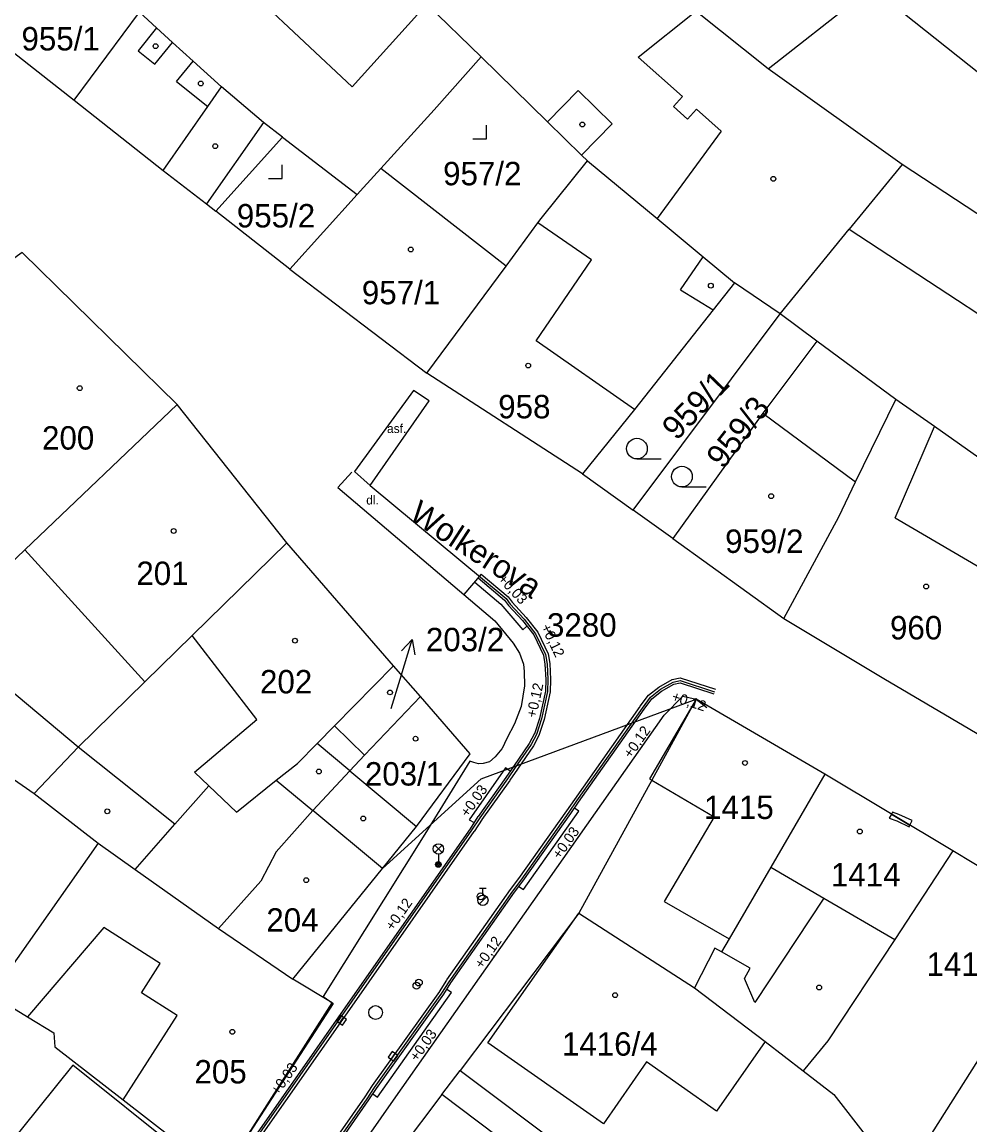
# Model space of a CAD drawing. Extents: x -600849 to -599899, y -1204328 to -1203436.
# Drawn here: x -600363.4 to -600294.6, y -1203715.5 to -1203635.4 of the extents above; entities that cross this region are included whole.
import ezdxf

# ---------------------------------------------------------------- set-up
doc = ezdxf.new("R2010")
doc.units = 0
for name, color, linetype in [('Vrstva 1', 7, 'Continuous'), ('Vrstva 10', 7, 'Continuous'), ('Vrstva 11', 7, 'Continuous'), ('Vrstva 13', 7, 'Continuous'), ('Vrstva 2', 7, 'Continuous'), ('Vrstva 27', 7, 'Continuous'), ('Vrstva 28', 7, 'Continuous'), ('Vrstva 3', 7, 'Continuous'), ('Vrstva 33', 7, 'Continuous'), ('Vrstva 4', 7, 'Continuous'), ('Vrstva 40', 7, 'Continuous'), ('Vrstva 42', 7, 'Continuous'), ('Vrstva 5', 7, 'Continuous'), ('Vrstva 7', 7, 'Continuous')]:
    doc.layers.add(name, color=color, linetype=linetype)

msp = doc.modelspace()

# ---------------------------------------------------------------- linework, layer by layer
at = {"layer": 'Vrstva 1'}
for p, q in [((-600309.22, -1203638.82), (-600301.72, -1203632.94)), ((-600366.05, -1203636.05), (-600359.62, -1203641.11)), ((-600333.47, -1203641.81), (-600330.07, -1203637.95)), ((-600359.62, -1203641.11), (-600353.15, -1203646.2)), ((-600337.36, -1203646.05), (-600333.47, -1203641.81)), ((-600349.33, -1203649.16), (-600344.49, -1203643.78)), ((-600344.49, -1203643.78), (-600339.08, -1203647.96)), ((-600328.26, -1203653.15), (-600337.36, -1203646.05)), ((-600339.08, -1203647.96), (-600343.95, -1203653.36)), ((-600343.95, -1203653.36), (-600349.33, -1203649.16)), ((-600328.26, -1203653.15), (-600325.94, -1203650.01)), ((-600343.95, -1203653.36), (-600334.01, -1203660.91)), ((-600334.01, -1203660.91), (-600328.26, -1203653.15)), ((-600308.36, -1203656.62), (-600311.66, -1203654.37)), ((-600319.02, -1203670.87), (-600308.36, -1203656.62)), ((-600305.68, -1203658.6), (-600308.36, -1203656.62)), ((-600299.96, -1203662.82), (-600305.68, -1203658.6)), ((-600322.7, -1203668.24), (-600334.01, -1203660.91)), ((-600344.18, -1203673.23), (-600352.14, -1203663.19)), ((-600302.87, -1203668.82), (-600299.96, -1203662.82)), ((-600318.92, -1203663.55), (-600322.7, -1203668.24)), ((-600322.7, -1203668.24), (-600319.02, -1203670.87)), ((-600316.15, -1203672.93), (-600319.02, -1203670.87)), ((-600316.15, -1203672.93), (-600308.08, -1203678.72)), ((-600336.42, -1203682.16), (-600344.18, -1203673.23)), ((-600340.71, -1203686.52), (-600336.42, -1203682.16)), ((-600334.48, -1203684.39), (-600336.42, -1203682.16)), ((-600305.11, -1203690.04), (-600314.45, -1203684.58)), ((-600295.8, -1203695.61), (-600305.11, -1203690.04)), ((-600362.52, -1203691.44), (-600357.88, -1203695.04)), ((-600337.24, -1203696.89), (-600334.76, -1203693.83)), ((-600357.88, -1203695.04), (-600365.63, -1203706.06)), ((-600357.88, -1203695.04), (-600355.19, -1203696.95)), ((-600287.54, -1203700.59), (-600295.8, -1203695.61)), ((-600343.75, -1203704.92), (-600337.24, -1203696.89)), ((-600322.98, -1203700.12), (-600331.6, -1203711.54)), ((-600322.98, -1203700.12), (-600314.57, -1203705.54)), ((-600287.54, -1203700.59), (-600299.56, -1203719.57)), ((-600340.89, -1203706.64), (-600343.75, -1203704.92)), ((-600314.57, -1203705.54), (-600309.44, -1203709.45)), ((-600348.91, -1203719.22), (-600340.89, -1203706.64)), ((-600309.44, -1203709.45), (-600306.67, -1203711.58)), ((-600332.92, -1203713.3), (-600331.6, -1203711.54)), ((-600331.6, -1203711.54), (-600311.99, -1203726.24)), ((-600332.92, -1203713.3), (-600339.11, -1203721.5)), ((-600314.72, -1203726.98), (-600332.92, -1203713.3))]:
    msp.add_line(p, q, dxfattribs=at)
for points in [[(-600330.07, -1203637.95), (-600334.01, -1203634.13), (-600341.44, -1203626.9), (-600343.88, -1203624.53), (-600348.59, -1203618.67)], [(-600309.22, -1203638.82), (-600314.48, -1203634.64), (-600317.23, -1203632.11)], [(-600344.49, -1203643.78), (-600345.86, -1203642.72), (-600348.93, -1203640.13), (-600350.99, -1203638.26), (-600352.47, -1203636.91), (-600353.63, -1203635.85), (-600354.88, -1203634.71)], [(-600299.45, -1203634.74), (-600278.65, -1203651.25), (-600263.23, -1203661.57), (-600241.56, -1203672.31)], [(-600322.35, -1203645.5), (-600322.77, -1203645.09), (-600325.25, -1203642.67), (-600330.07, -1203637.95)], [(-600282.53, -1203656.9), (-600299.5, -1203645.77), (-600309.22, -1203638.82)], [(-600325.94, -1203650.01), (-600325.71, -1203649.7), (-600322.35, -1203645.5)], [(-600322.35, -1203645.5), (-600317.29, -1203649.7), (-600313.95, -1203652.47), (-600311.66, -1203654.37)], [(-600353.15, -1203646.2), (-600350.01, -1203648.63), (-600349.33, -1203649.16)], [(-600339.08, -1203647.96), (-600338.62, -1203647.44), (-600337.36, -1203646.05)], [(-600308.36, -1203656.62), (-600303.33, -1203650.46), (-600286.14, -1203661.75), (-600282.53, -1203656.9)], [(-600352.14, -1203663.19), (-600363.4, -1203652.15), (-600364.16, -1203652.72)], [(-600311.66, -1203654.37), (-600313.21, -1203656.33), (-600318.92, -1203663.55)], [(-600305.68, -1203658.6), (-600309.62, -1203663.83), (-600316.15, -1203672.93)], [(-600373.17, -1203683.31), (-600369.43, -1203679.61), (-600368.04, -1203678.14), (-600367.92, -1203678.25), (-600363.2, -1203673.74), (-600352.14, -1203663.19)], [(-600284.69, -1203673.58), (-600288.48, -1203670.91), (-600297.15, -1203664.8), (-600299.96, -1203662.82)], [(-600308.08, -1203678.72), (-600304.09, -1203671.35), (-600302.87, -1203668.82)], [(-600362.52, -1203691.44), (-600359.32, -1203688.08), (-600354.48, -1203683.34), (-600351.05, -1203679.97), (-600344.18, -1203673.23)], [(-600308.08, -1203678.72), (-600300.83, -1203683.09), (-600292.82, -1203687.81)], [(-600373.17, -1203683.31), (-600366.91, -1203688.4), (-600362.52, -1203691.44)], [(-600334.48, -1203684.39), (-600338.53, -1203688.66), (-600340.71, -1203686.52)], [(-600337.24, -1203696.89), (-600330.06, -1203690.37), (-600314.45, -1203684.58)], [(-600334.76, -1203693.83), (-600330.86, -1203688.56), (-600334.48, -1203684.39)], [(-600314.45, -1203684.58), (-600317.68, -1203690.47), (-600322.98, -1203700.12)], [(-600344.94, -1203690.48), (-600343.4, -1203689.26), (-600341.97, -1203687.81), (-600340.71, -1203686.52)], [(-600355.19, -1203696.95), (-600352.3, -1203693.66), (-600349.85, -1203690.87), (-600347.84, -1203692.79), (-600344.94, -1203690.48)], [(-600344.94, -1203690.48), (-600342.3, -1203692.68), (-600339.6, -1203689.79), (-600334.76, -1203693.83)], [(-600305.11, -1203690.04), (-600309.03, -1203696.78), (-600312.05, -1203701.98), (-600312.6, -1203702.94), (-600313.09, -1203702.67), (-600314.57, -1203705.54)], [(-600295.8, -1203695.61), (-600300.03, -1203702.03), (-600304.88, -1203709.39), (-600306.67, -1203711.58)], [(-600355.19, -1203696.95), (-600349.13, -1203701.25), (-600343.75, -1203704.92)], [(-600309.44, -1203709.45), (-600312.98, -1203714.49), (-600318.05, -1203710.93), (-600321.19, -1203715.42), (-600329.58, -1203709.54), (-600322.98, -1203700.12)], [(-600365.63, -1203706.06), (-600363, -1203707.66), (-600361.09, -1203708.81), (-600361.02, -1203709.84), (-600356.07, -1203713.68), (-600348.91, -1203719.22)], [(-600306.67, -1203711.58), (-600304.45, -1203713.29), (-600299.56, -1203719.57)]]:
    msp.add_lwpolyline(points, dxfattribs=at)
at = {"layer": 'Vrstva 10'}
for p, q in [((-600339.26, -1203668.07), (-600338.12, -1203669.07)), ((-600338.12, -1203669.07), (-600328.25, -1203677.29)), ((-600328.25, -1203677.29), (-600327.97, -1203677.68)), ((-600327.97, -1203677.68), (-600326.95, -1203678.78)), ((-600326.95, -1203678.78), (-600326.12, -1203679.84)), ((-600326.12, -1203679.84), (-600325.39, -1203681.35)), ((-600325.39, -1203681.35), (-600325.28, -1203682.04)), ((-600325.28, -1203682.04), (-600325.22, -1203683.16)), ((-600325.22, -1203683.16), (-600325.25, -1203684.03)), ((-600316.12, -1203683.36), (-600315.61, -1203683.24)), ((-600315.61, -1203683.24), (-600313.12, -1203684.05)), ((-600325.25, -1203684.03), (-600325.68, -1203686.02)), ((-600317.77, -1203684.45), (-600317.04, -1203683.87)), ((-600317.04, -1203683.87), (-600316.12, -1203683.36)), ((-600318.35, -1203685.23), (-600317.77, -1203684.45)), ((-600323.11, -1203691.98), (-600318.35, -1203685.23)), ((-600325.68, -1203686.02), (-600326.05, -1203687.15)), ((-600326.05, -1203687.15), (-600326.44, -1203687.87)), ((-600326.44, -1203687.87), (-600327.6, -1203689.55)), ((-600327.6, -1203689.55), (-600328.14, -1203690.36)), ((-600328.14, -1203690.36), (-600330.17, -1203693.2)), ((-600323.68, -1203692.8), (-600323.11, -1203691.98)), ((-600327.17, -1203697.72), (-600323.68, -1203692.8)), ((-600330.17, -1203693.2), (-600330.76, -1203694.1)), ((-600330.76, -1203694.1), (-600339.46, -1203706.52)), ((-600327.76, -1203698.52), (-600327.17, -1203697.72)), ((-600332.39, -1203705.1), (-600327.76, -1203698.52)), ((-600332.91, -1203705.94), (-600332.39, -1203705.1)), ((-600339.46, -1203706.52), (-600348.58, -1203719.55)), ((-600337.8, -1203712.77), (-600332.91, -1203705.94)), ((-600338.34, -1203713.6), (-600337.8, -1203712.77)), ((-600345.81, -1203724.26), (-600338.34, -1203713.6))]:
    msp.add_line(p, q, dxfattribs=at)
at = {"layer": 'Vrstva 11'}
for p, q in [((-600334.98, -1203662.19), (-600339.26, -1203668.07)), ((-600333.84, -1203662.94), (-600334.98, -1203662.19)), ((-600338.12, -1203669.07), (-600333.84, -1203662.94)), ((-600339.458, -1203668.096), (-600340.47, -1203669.22)), ((-600340.47, -1203669.22), (-600329.06, -1203678.9)), ((-600330.062, -1203675.52), (-600331.311, -1203676.99)), ((-600330.53, -1203676.09), (-600328.64, -1203677.68)), ((-600330.289, -1203675.787), (-600328.361, -1203677.393)), ((-600330.062, -1203675.52), (-600328.102, -1203677.153)), ((-600328.64, -1203677.68), (-600327.04, -1203679.56)), ((-600328.361, -1203677.393), (-600328.085, -1203677.776)), ((-600328.102, -1203677.153), (-600327.814, -1203677.554)), ((-600327.814, -1203677.554), (-600326.793, -1203678.655)), ((-600328.085, -1203677.776), (-600327.061, -1203678.881)), ((-600329.06, -1203678.9), (-600327.73, -1203680.52)), ((-600327.061, -1203678.881), (-600326.248, -1203679.919)), ((-600327.04, -1203679.56), (-600326.74, -1203679.3)), ((-600326.793, -1203678.655), (-600325.951, -1203679.73)), ((-600326.248, -1203679.919), (-600325.535, -1203681.395)), ((-600325.951, -1203679.73), (-600325.197, -1203681.291)), ((-600327.73, -1203680.52), (-600327.27, -1203681.26)), ((-600327.27, -1203681.26), (-600326.98, -1203682.05)), ((-600325.535, -1203681.395), (-600325.43, -1203682.053)), ((-600325.197, -1203681.291), (-600325.082, -1203682.008)), ((-600326.98, -1203682.05), (-600326.943, -1203682.579)), ((-600325.43, -1203682.053), (-600325.37, -1203683.163)), ((-600325.082, -1203682.008), (-600325.02, -1203683.167)), ((-600326.943, -1203682.579), (-600326.91, -1203683.62)), ((-600325.37, -1203683.163), (-600325.399, -1203684.009)), ((-600325.02, -1203683.167), (-600325.05, -1203684.051)), ((-600317.155, -1203683.705), (-600316.192, -1203683.171)), ((-600316.192, -1203683.171), (-600315.602, -1203683.033)), ((-600315.602, -1203683.033), (-600313.058, -1203683.86)), ((-600326.91, -1203683.62), (-600327.17, -1203685.11)), ((-600325.399, -1203684.009), (-600325.825, -1203685.98)), ((-600325.05, -1203684.051), (-600325.488, -1203686.076)), ((-600317.914, -1203684.308), (-600317.155, -1203683.705)), ((-600317.66, -1203684.554), (-600316.959, -1203683.997)), ((-600316.959, -1203683.997), (-600316.065, -1203683.501)), ((-600316.065, -1203683.501), (-600315.617, -1203683.396)), ((-600315.617, -1203683.396), (-600313.166, -1203684.193)), ((-600318.508, -1203685.106), (-600317.914, -1203684.308)), ((-600318.227, -1203685.315), (-600317.66, -1203684.554)), ((-600316.77, -1203685.75), (-600315.41, -1203684.36)), ((-600315.41, -1203684.36), (-600314.45, -1203684.58)), ((-600314.45, -1203684.58), (-600313.67, -1203685.19)), ((-600336.42, -1203713.7), (-600316.77, -1203685.75)), ((-600327.17, -1203685.11), (-600327.64, -1203686.38)), ((-600323.273, -1203691.864), (-600318.513, -1203685.113)), ((-600322.987, -1203692.066), (-600318.227, -1203685.315)), ((-600327.64, -1203686.38), (-600328.19, -1203687.45)), ((-600325.825, -1203685.98), (-600326.193, -1203687.103)), ((-600325.488, -1203686.076), (-600325.867, -1203687.233)), ((-600326.182, -1203687.079), (-600326.57, -1203687.795)), ((-600325.867, -1203687.233), (-600326.27, -1203687.976)), ((-600328.19, -1203687.45), (-600328.54, -1203688.17)), ((-600326.57, -1203687.795), (-600327.723, -1203689.465)), ((-600326.27, -1203687.976), (-600327.435, -1203689.664)), ((-600329.04, -1203688.78), (-600329.45, -1203689.14)), ((-600328.57, -1203688.2), (-600329.04, -1203688.78)), ((-600328.54, -1203688.17), (-600328.57, -1203688.2)), ((-600330.88, -1203689.08), (-600334.15, -1203694.38)), ((-600328.3, -1203689.57), (-600330.93, -1203693.34)), ((-600330.6, -1203689.18), (-600330.88, -1203689.08)), ((-600330.26, -1203689.29), (-600330.6, -1203689.18)), ((-600329.91, -1203689.25), (-600330.26, -1203689.29)), ((-600329.45, -1203689.14), (-600329.91, -1203689.25)), ((-600327.954, -1203689.811), (-600328.3, -1203689.57)), ((-600327.725, -1203689.467), (-600328.267, -1203690.28)), ((-600327.434, -1203689.661), (-600327.976, -1203690.474)), ((-600328.267, -1203690.28), (-600330.292, -1203693.113)), ((-600327.982, -1203690.484), (-600330.007, -1203693.317)), ((-600323.844, -1203692.686), (-600323.274, -1203691.866)), ((-600323.557, -1203692.886), (-600322.987, -1203692.066)), ((-600327.333, -1203697.605), (-600323.843, -1203692.685)), ((-600327.048, -1203697.807), (-600323.558, -1203692.887)), ((-600326.99, -1203698.4), (-600322.97, -1203692.71)), ((-600322.97, -1203692.71), (-600323.28, -1203692.5)), ((-600330.93, -1203693.34), (-600330.566, -1203693.532)), ((-600330.295, -1203693.118), (-600330.873, -1203694)), ((-600330.002, -1203693.31), (-600330.58, -1203694.192)), ((-600334.15, -1203694.38), (-600341.55, -1203706.18)), ((-600330.873, -1203694), (-600339.583, -1203706.434)), ((-600330.586, -1203694.201), (-600339.296, -1203706.635)), ((-600327.923, -1203698.404), (-600327.331, -1203697.601)), ((-600332.547, -1203704.977), (-600327.927, -1203698.411)), ((-600327.641, -1203698.612), (-600327.049, -1203697.809)), ((-600327.33, -1203698.18), (-600326.99, -1203698.4)), ((-600332.261, -1203705.178), (-600327.641, -1203698.612)), ((-600333.078, -1203705.832), (-600332.559, -1203704.994)), ((-600332.78, -1203706.016), (-600332.261, -1203705.178)), ((-600332.22, -1203705.88), (-600332.55, -1203705.66)), ((-600339.583, -1203706.434), (-600348.701, -1203719.462)), ((-600341.55, -1203706.18), (-600340.82, -1203706.68)), ((-600337.95, -1203712.635), (-600333.065, -1203705.812)), ((-600337.67, -1203712.846), (-600332.78, -1203706.016)), ((-600337.6, -1203713.49), (-600332.22, -1203705.88)), ((-600340.82, -1203706.68), (-600349.16, -1203719.55)), ((-600339.296, -1203706.635), (-600348.42, -1203719.672)), ((-600338.491, -1203713.467), (-600337.95, -1203712.635)), ((-600338.214, -1203713.682), (-600337.67, -1203712.846)), ((-600345.974, -1203724.145), (-600338.491, -1203713.467)), ((-600345.687, -1203724.346), (-600338.217, -1203713.686)), ((-600344.29, -1203724.94), (-600336.42, -1203713.7)), ((-600337.929, -1203713.244), (-600337.6, -1203713.49))]:
    msp.add_line(p, q, dxfattribs=at)
at = {"layer": 'Vrstva 13'}
for points in [[(-600298.94, -1203693.73), (-600300.27, -1203692.94), (-600300.44, -1203693.23), (-600299.87, -1203693.43), (-600298.99, -1203693.85)], [(-600300.19, -1203692.8), (-600300.27, -1203692.94), (-600298.94, -1203693.73), (-600298.77, -1203693.39), (-600299.73, -1203692.95)]]:
    msp.add_lwpolyline(points, close=True, dxfattribs=at)
at = {"layer": 'Vrstva 27'}
for p, q in [((-600340.341, -1203708.116), (-600340.059, -1203707.704)), ((-600336.603, -1203710.715), (-600336.317, -1203710.305))]:
    msp.add_line(p, q, dxfattribs=at)
for points in [[(-600340.135, -1203708.258), (-600339.852, -1203707.845), (-600340.265, -1203707.562), (-600340.548, -1203707.975)], [(-600336.398, -1203710.858), (-600336.112, -1203710.448), (-600336.522, -1203710.162), (-600336.808, -1203710.572)]]:
    msp.add_lwpolyline(points, close=True, dxfattribs=at)
msp.add_circle((-600337.73, -1203707.34), 0.5, dxfattribs=at)
at = {"layer": 'Vrstva 28'}
for p, q in [((-600330.19, -1203698.315), (-600329.69, -1203698.315)), ((-600329.94, -1203698.815), (-600329.94, -1203698.315)), ((-600330.198, -1203699.462), (-600329.668, -1203698.932))]:
    msp.add_line(p, q, dxfattribs=at)
for centre, radius in [((-600330.1, -1203698.91), 0.25), ((-600329.94, -1203699.19), 0.375), ((-600334.59, -1203705.16), 0.25), ((-600334.76, -1203705.39), 0.25)]:
    msp.add_circle(centre, radius, dxfattribs=at)
at = {"layer": 'Vrstva 3'}
for p, q in [((-600329.67, -1203643.91), (-600329.67, -1203642.91)), ((-600330.671, -1203643.91), (-600329.67, -1203643.91)), ((-600344.51, -1203646.79), (-600344.51, -1203645.79)), ((-600345.511, -1203646.79), (-600344.51, -1203646.79)), ((-600318.753, -1203667.15), (-600317.003, -1203667.15)), ((-600315.483, -1203669.18), (-600313.733, -1203669.18))]:
    msp.add_line(p, q, dxfattribs=at)
for centre in [(-600318.753, -1203666.4), (-600315.483, -1203668.43)]:
    msp.add_circle(centre, 0.75, dxfattribs=at)
at = {"layer": 'Vrstva 33'}
for p, q in [((-600333.435, -1203695.73), (-600332.905, -1203695.2)), ((-600333.435, -1203695.2), (-600332.905, -1203695.73)), ((-600333.17, -1203695.84), (-600333.17, -1203696.59))]:
    msp.add_line(p, q, dxfattribs=at)
for centre, radius in [((-600333.17, -1203695.465), 0.375), ((-600333.17, -1203696.59), 0.2), ((-600333.17, -1203696.59), 0.145), ((-600333.17, -1203696.59), 0.0876)]:
    msp.add_circle(centre, radius, dxfattribs=at)
at = {"layer": 'Vrstva 4'}
for p, q in [((-600350.23, -1203629.99), (-600339.44, -1203640.12)), ((-600339.44, -1203640.12), (-600334.01, -1203634.13)), ((-600359.62, -1203641.11), (-600354.88, -1203634.71)), ((-600318.67, -1203637.97), (-600314.48, -1203634.64)), ((-600353.63, -1203635.85), (-600354.98, -1203637.51)), ((-600354.98, -1203637.51), (-600353.77, -1203638.48)), ((-600353.77, -1203638.48), (-600352.47, -1203636.91)), ((-600352.18, -1203639.75), (-600350.99, -1203638.26)), ((-600318.67, -1203637.97), (-600315.45, -1203640.83)), ((-600352.18, -1203639.75), (-600349.92, -1203641.56)), ((-600349.92, -1203641.56), (-600348.93, -1203640.13)), ((-600325.25, -1203642.67), (-600323.03, -1203640.4)), ((-600323.03, -1203640.4), (-600320.55, -1203642.83)), ((-600315.45, -1203640.83), (-600316.1, -1203641.56)), ((-600353.15, -1203646.2), (-600349.92, -1203641.56)), ((-600316.1, -1203641.56), (-600315.07, -1203642.49)), ((-600315.07, -1203642.49), (-600314.42, -1203641.75)), ((-600314.42, -1203641.75), (-600312.63, -1203643.34)), ((-600345.86, -1203642.72), (-600350.01, -1203648.63)), ((-600320.55, -1203642.83), (-600322.77, -1203645.09)), ((-600312.63, -1203643.34), (-600317.29, -1203649.7)), ((-600299.5, -1203645.77), (-600303.33, -1203650.46)), ((-600322.04, -1203652.69), (-600325.94, -1203650.01)), ((-600326.06, -1203658.57), (-600322.04, -1203652.69)), ((-600315.59, -1203654.86), (-600313.95, -1203652.47)), ((-600315.59, -1203654.86), (-600313.21, -1203656.33)), ((-600318.92, -1203663.55), (-600326.06, -1203658.57)), ((-600309.62, -1203663.83), (-600302.87, -1203668.82)), ((-600299.99, -1203671.42), (-600297.15, -1203664.8)), ((-600299.99, -1203671.42), (-600291.99, -1203676.11)), ((-600363.2, -1203673.74), (-600354.48, -1203683.34)), ((-600359.32, -1203688.08), (-600369.43, -1203679.61)), ((-600346.36, -1203686.07), (-600351.05, -1203679.97)), ((-600314.45, -1203684.58), (-600317.85, -1203690.37)), ((-600350.88, -1203689.88), (-600346.36, -1203686.07)), ((-600352.3, -1203693.66), (-600359.32, -1203688.08)), ((-600339.6, -1203689.79), (-600341.97, -1203687.81)), ((-600338.53, -1203688.66), (-600339.6, -1203689.79)), ((-600349.85, -1203690.87), (-600350.88, -1203689.88)), ((-600317.85, -1203690.37), (-600317.68, -1203690.47)), ((-600317.68, -1203690.47), (-600313.15, -1203693.12)), ((-600342.3, -1203692.68), (-600344.95, -1203695.67)), ((-600337.24, -1203696.89), (-600342.3, -1203692.68)), ((-600313.15, -1203693.12), (-600316.78, -1203699.27)), ((-600344.95, -1203695.67), (-600346.07, -1203697.81)), ((-600309.03, -1203696.78), (-600305.17, -1203699.03)), ((-600346.07, -1203697.81), (-600349.13, -1203701.25)), ((-600316.78, -1203699.27), (-600312.05, -1203701.98)), ((-600305.17, -1203699.03), (-600310.19, -1203706.6)), ((-600305.17, -1203699.03), (-600300.03, -1203702.03)), ((-600357.46, -1203701.17), (-600363, -1203707.66)), ((-600353.37, -1203703.79), (-600357.46, -1203701.17)), ((-600310.53, -1203704.12), (-600312.6, -1203702.94)), ((-600354.73, -1203705.91), (-600353.37, -1203703.79)), ((-600310.95, -1203704.87), (-600310.53, -1203704.12)), ((-600310.19, -1203706.6), (-600310.95, -1203704.87)), ((-600352.15, -1203707.56), (-600354.73, -1203705.91)), ((-600356.07, -1203713.68), (-600352.15, -1203707.56)), ((-600359.72, -1203711.15), (-600367.63, -1203721.01)), ((-600352.03, -1203717.3), (-600359.72, -1203711.15))]:
    msp.add_line(p, q, dxfattribs=at)
at = {"layer": 'Vrstva 5'}
for centre in [(-600353.707, -1203637.179), (-600350.427, -1203639.889), (-600322.717, -1203642.869), (-600349.377, -1203644.439), (-600308.847, -1203646.809), (-600335.177, -1203651.939), (-600313.387, -1203654.569), (-600326.647, -1203660.369), (-600359.217, -1203662.009), (-600309.007, -1203669.849), (-600352.397, -1203672.379), (-600297.747, -1203676.409), (-600343.587, -1203680.339), (-600336.687, -1203684.099), (-600334.827, -1203687.459), (-600341.847, -1203689.839), (-600310.907, -1203689.219), (-600357.217, -1203692.729), (-600338.627, -1203693.249), (-600302.567, -1203694.199), (-600342.767, -1203697.729), (-600305.517, -1203705.519), (-600320.337, -1203706.079), (-600348.137, -1203708.739)]:
    msp.add_circle(centre, 0.175, dxfattribs=at)
at = {"layer": 'Vrstva 7'}
for p, q in [((-600335.95, -1203683.13), (-600335.073, -1203680.26)), ((-600335.073, -1203680.26), (-600335.844, -1203681.071)), ((-600335.073, -1203680.26), (-600334.887, -1203681.364)), ((-600336.59, -1203685.26), (-600335.95, -1203683.13))]:
    msp.add_line(p, q, dxfattribs=at)

# ---------------------------------------------------------------- texts
at = {"layer": 'Vrstva 2'}
for s, p in [('955/1', (-600363.448, -1203637.49)), ('957/2', (-600332.828, -1203647.28)), ('955/2', (-600347.808, -1203650.34)), ('957/1', (-600338.728, -1203655.92)), ('958', (-600328.825, -1203664.2)), ('200', (-600361.955, -1203666.47)), ('959/2', (-600312.348, -1203673.97)), ('201', (-600355.105, -1203676.3)), ('3280', (-600325.284, -1203680.05)), ('960', (-600300.375, -1203680.25)), ('203/2', (-600334.08, -1203681.11)), ('202', (-600346.125, -1203684.17)), ('203/1', (-600338.508, -1203690.86)), ('1415', (-600313.874, -1203693.29)), ('1414', (-600304.664, -1203698.18)), ('204', (-600345.665, -1203701.47)), ('1413', (-600297.724, -1203704.68)), ('1416/4', (-600324.197, -1203710.47)), ('205', (-600350.885, -1203712.49))]:
    msp.add_text(s, height=1.7, dxfattribs=at).set_placement(p)
for s, rotation, p in [('959/1', 46, (-600315.869, -1203665.873)), ('959/3', 52, (-600312.5, -1203667.952))]:
    msp.add_text(s, height=1.7, rotation=rotation, dxfattribs=at).set_placement(p)
at = {"layer": 'Vrstva 40'}
for s, p in [('asf.', (-600336.9, -1203665.265)), ('dl.', (-600338.411, -1203670.455))]:
    msp.add_text(s, height=0.65, dxfattribs=at).set_placement(p)
at = {"layer": 'Vrstva 42'}
for s, rotation, p in [('+0,03', 312.83892, (-600328.905, -1203675.911)), ('+0,12', 295.78344, (-600325.747, -1203679.345)), ('+0,12', 77.80404, (-600326.073, -1203685.984)), ('+0,12', 341.98685, (-600316.288, -1203684.702)), ('+0,12', 54.80907, (-600319.193, -1203688.942)), ('+0,03', 54.44324, (-600331.037, -1203693.21)), ('+0,03', 54.65003, (-600324.358, -1203696.262)), ('+0,12', 54.98881, (-600336.474, -1203701.453)), ('+0,12', 54.86796, (-600329.995, -1203704.216)), ('+0,03', 54.39889, (-600334.716, -1203710.953)), ('+0,03', 55.0127, (-600344.8, -1203713.398))]:
    msp.add_text(s, height=0.75, rotation=rotation, dxfattribs=at).set_placement(p)
at = {"layer": 'Vrstva 7'}
msp.add_text('Wolkerova', height=1.7, rotation=327, dxfattribs=at).set_placement((-600335.399, -1203671.49))

doc.saveas('drawing.dxf')
